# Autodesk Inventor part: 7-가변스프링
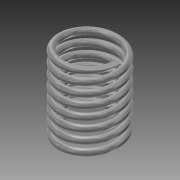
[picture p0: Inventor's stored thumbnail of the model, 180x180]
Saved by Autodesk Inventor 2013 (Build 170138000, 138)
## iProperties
Created: 2014-12
Part Number: 7-가변스프링
Material: 강철, 탄소
Document SubType Name: Modeling
Designer: cad10
Density: 7.87 g/cm^3
Mass: 80.13 g
Surface Area: 103.216 cm^2
Volume: 10.1817 cm^3
Author: cad10
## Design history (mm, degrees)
sketch "스케치1"
  geometry: L1 (0, 0)-(17.5, 0); L2 (17.5, 0)-(17.5, 48.5); L3 (17.5, 48.5)-(0, 48.5); L4 (0, 48.5)-(0, 0); C1 r 2 at (17.5, 0)
  constraints: 8 end point, 2 parallel, 1 centre point, 1 coincident, 1 horizontal, 1 perpendicular
  dimensions: "d0" = 4 diameter of C1; "d2" = 48.5 distance between parallel lines of L1 L3 (derived); "d3" = 35 diameter of L2 L4
feature "코일1" sketch "스케치1" pitch "d4" = 10; turns "d6" = 7.5; dims "d5" = 48.5 (= d2), "d7" = 0, angle "d8" = 90 deg, angle "d9" = 90 deg, "d10" = 0, "d11" = 0
sketch "스케치2"
  geometry: L1 (-19.5, 0)-(-15.5, 0) reference; 1 further point
  constraints: 1 horizontal alignment
extrude "돌출1" cut sketch "스케치2" distance "d12" = 10; taper "d13" = 0 deg
node "작업 평면1"
sketch "스케치3"
  geometry: L1 (15.5, 0)-(19.5, 0) reference; 1 further point
  constraints: 1 horizontal alignment
extrude "돌출2" cut sketch "스케치3" stored distance "d14" = 10; taper "d15" = 0 deg
node "솔리드1"
node "절단 모서리 투영1"
node "절단 모서리 투영2"
